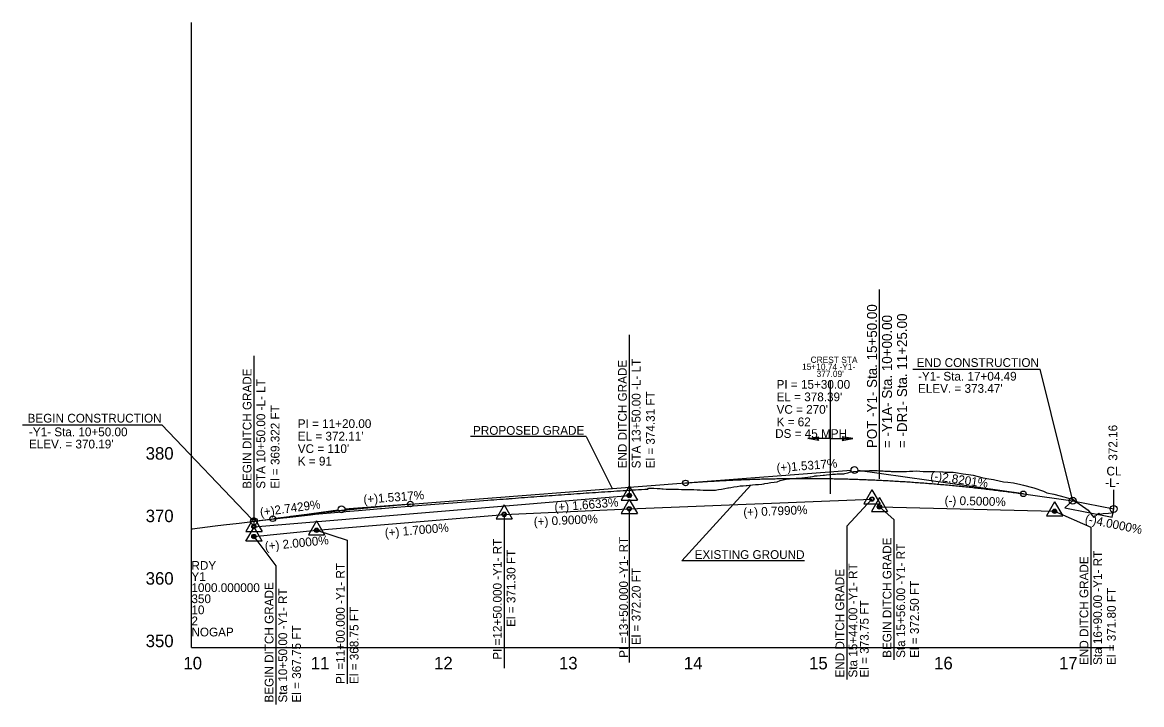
# Model space of a CAD drawing. Extents: x 1625686 to 1640492, y 1161393 to 1175642.
# Drawn here: x 1630069 to 1630964, y 1173490 to 1174036 of the extents above; entities that cross this region are included whole.
import ezdxf

# ---------------------------------------------------------------- set-up
doc = ezdxf.new("R2010")
doc.units = 0
for name, color, linetype in [('Exist Profile Cell', 7, 'Continuous'), ('Exist Vertical Profile Ground Line', 7, 'Continuous'), ('Exist Vertical Profile Horizontal Axis Label Major', 7, 'Continuous'), ('Exist Vertical Profile Vertical Axis Label', 7, 'Continuous'), ('Prop PFL Text', 7, 'Continuous'), ('Prop Plan Preparation Crest', 7, 'Continuous'), ('Prop Vertical Profile Curve Label', 7, 'Continuous'), ('Prop Vertical Profile Ditch Grade Left', 7, 'Continuous'), ('Prop Vertical Profile Ditch Grade Left Label', 7, 'Continuous'), ('Prop Vertical Profile Ditch Grade Right', 7, 'Continuous'), ('Prop Vertical Profile Ditch Grade Right Label', 7, 'Continuous'), ('Prop Vertical Profile Grade', 7, 'Continuous'), ('Prop Vertical Profile Grade Label', 7, 'Continuous'), ('Prop VPI Ditch Grade Left Label', 7, 'Continuous'), ('Prop VPI Ditch Grade Right Label', 7, 'Continuous'), ('Prop VPI Label', 7, 'Continuous')]:
    doc.layers.add(name, color=color, linetype=linetype)

msp = doc.modelspace()

# ---------------------------------------------------------------- linework, layer by layer
at = {"layer": 'Exist Profile Cell'}
for q in [(1630204.31, 1174035.94), (1630941.55, 1173535.94), (1630204.31, 1173535.94)]:
    msp.add_line((1630204.31, 1173535.94), q, dxfattribs=at)
at = {"layer": 'Exist Vertical Profile Ground Line'}
msp.add_lwpolyline([(1630204.31, 1173629.69), (1630205.03, 1173630.93), (1630223.37, 1173633.15), (1630230.03, 1173633.96), (1630242.43, 1173635.46), (1630255.29, 1173637.02), (1630261.5, 1173637.73), (1630280.07, 1173639.86), (1630280.56, 1173639.92), (1630299.62, 1173642.1), (1630305.07, 1173642.73), (1630305.57, 1173642.78), (1630306.15, 1173642.83), (1630318.68, 1173643.91), (1630330.85, 1173644.96), (1630337.74, 1173645.56), (1630352.81, 1173646.86), (1630355.57, 1173647.1), (1630356.33, 1173647.16), (1630362.04, 1173647.62), (1630381.43, 1173649.18), (1630405.79, 1173651.14), (1630406.14, 1173651.16), (1630430.79, 1173653), (1630431.14, 1173653.02), (1630441.12, 1173653.76), (1630443.58, 1173653.94), (1630446.04, 1173654.12), (1630448.5, 1173654.3), (1630450.96, 1173654.48), (1630453.42, 1173654.65), (1630455.89, 1173654.82), (1630457.71, 1173654.95), (1630458.58, 1173655.02), (1630460.81, 1173655.2), (1630463.27, 1173655.4), (1630465.73, 1173655.59), (1630468.19, 1173655.78), (1630470.65, 1173655.97), (1630473.11, 1173656.16), (1630475.57, 1173656.34), (1630478.04, 1173656.53), (1630480.5, 1173656.71), (1630482.96, 1173656.89), (1630485.42, 1173657.08), (1630486.7, 1173657.18), (1630487.88, 1173657.26), (1630490.34, 1173657.44), (1630492.8, 1173657.61), (1630495.26, 1173657.78), (1630497.72, 1173657.95), (1630500.19, 1173658.12), (1630502.65, 1173658.29), (1630505.11, 1173658.45), (1630506.91, 1173658.57), (1630507.57, 1173658.62), (1630510.03, 1173658.8), (1630512.49, 1173658.98), (1630514.95, 1173659.16), (1630517.41, 1173659.34), (1630517.82, 1173659.37), (1630519.87, 1173659.51), (1630522.33, 1173659.68), (1630524.8, 1173659.84), (1630527.26, 1173660), (1630529.72, 1173660.17), (1630532.18, 1173660.33), (1630534.64, 1173660.49), (1630537.1, 1173660.66), (1630539.56, 1173660.82), (1630542.02, 1173660.98), (1630544.48, 1173661.14), (1630546.95, 1173661.3), (1630549.41, 1173661.46), (1630551.87, 1173661.61), (1630554.33, 1173661.76), (1630555.63, 1173661.84), (1630556.79, 1173661.91), (1630557.13, 1173661.93), (1630558.17, 1173662.01), (1630559.38, 1173662.09), (1630561.71, 1173662.24), (1630564.17, 1173662.4), (1630566.63, 1173662.55), (1630569.22, 1173662.65), (1630569.8, 1173663.44), (1630571.56, 1173663.36), (1630574.02, 1173663.26), (1630576.48, 1173663.15), (1630578.94, 1173663.04), (1630580.36, 1173662.97), (1630581.4, 1173662.89), (1630583.86, 1173662.68), (1630585.01, 1173662.59), (1630586.32, 1173662.57), (1630588.78, 1173662.55), (1630591.25, 1173662.51), (1630593.24, 1173662.48), (1630593.71, 1173662.47), (1630596.17, 1173662.39), (1630597.12, 1173662.36), (1630598.63, 1173662.35), (1630601.09, 1173662.34), (1630603.55, 1173662.31), (1630604.98, 1173662.3), (1630606.01, 1173662.24), (1630608.47, 1173662.11), (1630610.93, 1173661.97), (1630613.4, 1173661.82), (1630615.86, 1173661.67), (1630616.16, 1173661.65), (1630618.32, 1173661.73), (1630620.78, 1173661.81), (1630623.24, 1173661.9), (1630624.2, 1173661.93), (1630625.7, 1173662.21), (1630628.16, 1173662.67), (1630630.62, 1173663.12), (1630633.08, 1173663.58), (1630633.7, 1173663.69), (1630635.54, 1173664), (1630638.01, 1173664.42), (1630640.47, 1173664.83), (1630642.93, 1173665.24), (1630643.49, 1173665.33), (1630645.39, 1173665.36), (1630647.85, 1173665.39), (1630648.61, 1173665.4), (1630650.31, 1173665.66), (1630652.77, 1173666.03), (1630655.23, 1173666.36), (1630657.19, 1173666.21), (1630657.69, 1173666.29), (1630660.16, 1173666.7), (1630661.74, 1173666.96), (1630662.62, 1173667.09), (1630665.08, 1173667.45), (1630666.09, 1173667.61), (1630667.54, 1173667.82), (1630670, 1173668.17), (1630672.46, 1173668.57), (1630674.92, 1173669.38), (1630677.38, 1173670.15), (1630679.84, 1173670.62), (1630682.31, 1173670.85), (1630684.77, 1173671.08), (1630685.82, 1173671.18), (1630687.37, 1173671.2), (1630688.04, 1173671.35), (1630689.69, 1173671.48), (1630692.15, 1173671.67), (1630694.61, 1173671.85), (1630694.98, 1173671.88), (1630697.07, 1173672.16), (1630698.91, 1173672.4), (1630699.53, 1173672.53), (1630701.99, 1173673.02), (1630702.63, 1173673.15), (1630704.46, 1173673.3), (1630706.92, 1173673.5), (1630709.38, 1173673.7), (1630709.71, 1173673.73), (1630710.31, 1173673.75), (1630711.84, 1173673.96), (1630714.3, 1173674.22), (1630716.76, 1173674.49), (1630718.02, 1173674.62), (1630719.22, 1173674.66), (1630720.46, 1173674.71), (1630721.68, 1173674.75), (1630724.14, 1173674.84), (1630725.77, 1173674.9), (1630726.6, 1173675.12), (1630729.07, 1173675.76), (1630731.14, 1173676.31), (1630731.53, 1173676.37), (1630733.55, 1173676.72), (1630733.99, 1173676.75), (1630736.45, 1173676.94), (1630738.91, 1173677.14), (1630740.22, 1173677.24), (1630741.37, 1173677.26), (1630741.77, 1173677.33), (1630743.83, 1173677.35), (1630746.29, 1173677.38), (1630748.75, 1173677.4), (1630749.23, 1173677.41), (1630751.22, 1173677.43), (1630752.35, 1173677.45), (1630753.68, 1173677.36), (1630756.14, 1173677.19), (1630757.13, 1173677.12), (1630758.6, 1173677.05), (1630761.06, 1173676.93), (1630762.88, 1173676.84), (1630763.52, 1173676.81), (1630765.07, 1173676.73), (1630765.98, 1173676.72), (1630768.44, 1173676.7), (1630770.9, 1173676.67), (1630772.03, 1173676.66), (1630773.05, 1173676.64), (1630773.37, 1173676.64), (1630775.83, 1173676.78), (1630778.29, 1173676.92), (1630781.07, 1173677.08), (1630783.81, 1173677.12), (1630789.11, 1173676.71), (1630794.24, 1173676.81), (1630798.63, 1173676.8), (1630804.7, 1173676.38), (1630805.22, 1173676.38), (1630806.83, 1173676.25), (1630813.21, 1173676.06), (1630815.12, 1173675.88), (1630821.25, 1173674.93), (1630825.56, 1173674.28), (1630829.28, 1173673.7), (1630836, 1173671.95), (1630837.32, 1173671.57), (1630841.72, 1173670.89), (1630845.35, 1173670.37), (1630846.44, 1173670.13), (1630853.39, 1173668.51), (1630856.88, 1173668.08), (1630861.42, 1173667.53), (1630867.32, 1173666.28), (1630869.46, 1173665.71), (1630876.61, 1173663.87), (1630877.76, 1173663.58), (1630885.53, 1173660.86), (1630888.2, 1173659.74), (1630893.56, 1173658.51), (1630898.64, 1173657.34), (1630901.6, 1173656.45), (1630909.08, 1173654.2), (1630909.63, 1173653.98), (1630911.37, 1173652.69), (1630919.19, 1173647.2), (1630921.12, 1173645.83), (1630921.72, 1173644.96), (1630925.61, 1173639.94), (1630928.49, 1173642.62), (1630929.76, 1173643.51), (1630930.74, 1173642.63), (1630931.71, 1173642.77), (1630933.23, 1173643.03), (1630937.47, 1173643.48), (1630941.55, 1173643.97)], dxfattribs=at)
at = {"layer": 'Prop PFL Text'}
msp.add_line((1630754.31, 1173670.96), (1630754.31, 1173822.24), dxfattribs=at)
at = {"layer": 'Prop Plan Preparation Crest'}
for p, q in [((1630715.05, 1173658.9), (1630715.05, 1173748.84)), ((1630715.05, 1173702.98), (1630697.05, 1173702.98)), ((1630715.05, 1173702.98), (1630733.05, 1173702.98))]:
    msp.add_line(p, q, dxfattribs=at)
for points in [[(1630705.62, 1173701.56), (1630697.05, 1173702.98), (1630705.62, 1173704.41), (1630704.55, 1173702.98)], [(1630724.49, 1173701.56), (1630733.05, 1173702.98), (1630724.49, 1173704.41), (1630725.55, 1173702.98)]]:
    msp.add_lwpolyline(points, close=True, dxfattribs=at)
at = {"layer": 'Prop Vertical Profile Curve Label'}
for p, q in [((1630941.54, 1173646.74), (1630941.54, 1173661.93)), ((1630908.67, 1173653.31), (1630902.4, 1173647.76)), ((1630902.4, 1173647.76), (1630940.23, 1173640.19)), ((1630940.23, 1173640.19), (1630941.54, 1173646.74))]:
    msp.add_line(p, q, dxfattribs=at)
for centre in [(1630599.31, 1173667.55), (1630869.31, 1173658.85), (1630379.31, 1173650.7), (1630269.31, 1173638.95)]:
    msp.add_circle(centre, 2.25, dxfattribs=at)
at = {"layer": 'Prop Vertical Profile Ditch Grade Left'}
msp.add_line((1630254.31, 1173632.55), (1630554.31, 1173657.5), dxfattribs=at)
at = {"layer": 'Prop Vertical Profile Ditch Grade Right'}
msp.add_line((1630754.31, 1173648.44), (1630894.31, 1173644.94), dxfattribs=at)
msp.add_lwpolyline([(1630254.31, 1173624.69), (1630304.31, 1173629.69), (1630454.31, 1173642.44), (1630554.31, 1173646.94), (1630748.31, 1173654.69)], dxfattribs=at)
at = {"layer": 'Prop Vertical Profile Ditch Grade Right Label'}
for p, q in [((1630748.31, 1173662.17), (1630741.86, 1173650.97)), ((1630748.31, 1173662.17), (1630754.81, 1173650.97)), ((1630454.31, 1173649.92), (1630447.86, 1173638.72)), ((1630454.31, 1173649.92), (1630460.81, 1173638.72)), ((1630554.31, 1173654.42), (1630547.86, 1173643.22)), ((1630554.31, 1173654.42), (1630560.81, 1173643.22)), ((1630741.86, 1173650.97), (1630754.81, 1173650.97)), ((1630754.31, 1173655.92), (1630747.86, 1173644.72)), ((1630754.31, 1173655.92), (1630760.81, 1173644.72)), ((1630894.31, 1173652.37), (1630887.86, 1173641.17)), ((1630894.31, 1173652.37), (1630900.81, 1173641.17)), ((1630547.86, 1173643.22), (1630560.81, 1173643.22)), ((1630747.86, 1173644.72), (1630760.81, 1173644.72)), ((1630887.86, 1173641.17), (1630900.81, 1173641.17)), ((1630247.87, 1173620.95), (1630254.33, 1173632.17)), ((1630260.79, 1173620.95), (1630254.33, 1173632.17)), ((1630304.31, 1173637.17), (1630297.86, 1173625.97)), ((1630304.31, 1173637.17), (1630310.81, 1173625.97)), ((1630447.86, 1173638.72), (1630460.81, 1173638.72)), ((1630297.86, 1173625.97), (1630310.81, 1173625.97)), ((1630260.79, 1173620.95), (1630247.87, 1173620.95))]:
    msp.add_line(p, q, dxfattribs=at)
for centre, radius in [((1630748.31, 1173654.69), 1.75), ((1630748.31, 1173654.69), 1.2), ((1630754.31, 1173648.44), 1.75), ((1630754.31, 1173648.44), 1.2), ((1630454.31, 1173642.44), 1.75), ((1630454.31, 1173642.44), 1.2), ((1630554.31, 1173646.94), 1.75), ((1630554.31, 1173646.94), 1.2), ((1630894.31, 1173644.89), 1.75), ((1630894.31, 1173644.89), 1.2), ((1630304.31, 1173629.69), 1.75), ((1630254.31, 1173624.69), 1.75), ((1630254.31, 1173624.69), 1.2), ((1630304.31, 1173629.69), 1.2)]:
    msp.add_circle(centre, radius, dxfattribs=at)
at = {"layer": 'Prop Vertical Profile Grade'}
for p, q in [((1630379.31, 1173650.7), (1630599.31, 1173667.55)), ((1630869.31, 1173658.85), (1630908.8, 1173653.28)), ((1630908.8, 1173653.28), (1630941.54, 1173646.74)), ((1630254.31, 1173636.89), (1630269.31, 1173638.95))]:
    msp.add_line(p, q, dxfattribs=at)
for points in [[(1630599.31, 1173667.55), (1630604.71, 1173667.95), (1630610.11, 1173668.33), (1630615.51, 1173668.68), (1630620.91, 1173669.02), (1630626.31, 1173669.32), (1630631.71, 1173669.61), (1630637.11, 1173669.87), (1630642.51, 1173670.11), (1630647.91, 1173670.32), (1630653.31, 1173670.51), (1630658.71, 1173670.68), (1630664.11, 1173670.82), (1630669.51, 1173670.94), (1630674.91, 1173671.04), (1630680.31, 1173671.11), (1630685.71, 1173671.16), (1630691.11, 1173671.18), (1630696.51, 1173671.19), (1630701.91, 1173671.17), (1630707.31, 1173671.12), (1630712.71, 1173671.05), (1630718.11, 1173670.96), (1630723.51, 1173670.85), (1630728.91, 1173670.71), (1630734.31, 1173670.54), (1630739.71, 1173670.36), (1630745.11, 1173670.15), (1630750.51, 1173669.92), (1630755.91, 1173669.66), (1630761.31, 1173669.38), (1630766.71, 1173669.08), (1630772.11, 1173668.75), (1630777.51, 1173668.4), (1630782.91, 1173668.03), (1630788.31, 1173667.63), (1630793.71, 1173667.21), (1630799.11, 1173666.77), (1630804.51, 1173666.3), (1630809.91, 1173665.81), (1630815.31, 1173665.29), (1630820.71, 1173664.75), (1630826.11, 1173664.19), (1630831.51, 1173663.61), (1630836.91, 1173663), (1630842.31, 1173662.37), (1630847.71, 1173661.71), (1630853.11, 1173661.03), (1630858.51, 1173660.33), (1630863.91, 1173659.6), (1630869.31, 1173658.85)], [(1630269.31, 1173638.95), (1630271.51, 1173639.25), (1630273.71, 1173639.54), (1630275.91, 1173639.84), (1630278.11, 1173640.13), (1630280.31, 1173640.42), (1630282.51, 1173640.71), (1630284.71, 1173640.99), (1630286.91, 1173641.27), (1630289.11, 1173641.55), (1630291.31, 1173641.83), (1630293.51, 1173642.1), (1630295.71, 1173642.37), (1630297.91, 1173642.64), (1630300.11, 1173642.91), (1630302.31, 1173643.17), (1630304.51, 1173643.43), (1630306.71, 1173643.69), (1630308.91, 1173643.94), (1630311.11, 1173644.2), (1630313.31, 1173644.45), (1630315.51, 1173644.69), (1630317.71, 1173644.94), (1630319.91, 1173645.18), (1630322.11, 1173645.42), (1630324.31, 1173645.66), (1630326.51, 1173645.89), (1630328.71, 1173646.12), (1630330.91, 1173646.35), (1630333.11, 1173646.57), (1630335.31, 1173646.8), (1630337.51, 1173647.02), (1630339.71, 1173647.24), (1630341.91, 1173647.45), (1630344.11, 1173647.66), (1630346.31, 1173647.87), (1630348.51, 1173648.08), (1630350.71, 1173648.29), (1630352.91, 1173648.49), (1630355.11, 1173648.69), (1630357.31, 1173648.88), (1630359.51, 1173649.08), (1630361.71, 1173649.27), (1630363.91, 1173649.46), (1630366.11, 1173649.64), (1630368.31, 1173649.82), (1630370.51, 1173650.01), (1630372.71, 1173650.18), (1630374.91, 1173650.36), (1630377.11, 1173650.53), (1630379.31, 1173650.7)]]:
    msp.add_spline(points, degree=3, dxfattribs=at)
at = {"layer": 'Prop VPI Ditch Grade Left Label'}
for p, q in [((1630554.31, 1173785.99), (1630554.31, 1173657.5)), ((1630254.31, 1173769.15), (1630254.31, 1173632.55)), ((1630554.31, 1173664.98), (1630547.86, 1173653.78)), ((1630554.31, 1173664.98), (1630560.81, 1173653.78)), ((1630547.86, 1173653.78), (1630560.81, 1173653.78)), ((1630254.31, 1173640.03), (1630247.86, 1173628.83)), ((1630254.31, 1173640.03), (1630260.81, 1173628.83)), ((1630247.86, 1173628.83), (1630260.81, 1173628.83))]:
    msp.add_line(p, q, dxfattribs=at)
for centre, radius in [((1630554.31, 1173657.5), 1.75), ((1630554.31, 1173657.5), 1.2), ((1630554.31, 1173657.5), 0.5), ((1630254.31, 1173632.55), 1.75), ((1630254.31, 1173632.55), 1.2)]:
    msp.add_circle(centre, radius, dxfattribs=at)
at = {"layer": 'Prop VPI Ditch Grade Right Label'}
for p, q in [((1630454.31, 1173642.44), (1630454.31, 1173519.52)), ((1630554.31, 1173646.94), (1630554.31, 1173524.02))]:
    msp.add_line(p, q, dxfattribs=at)
for points in [[(1630748.31, 1173654.69), (1630728.09, 1173632.91), (1630728.09, 1173510.23)], [(1630754.31, 1173648.44), (1630765.81, 1173638.36), (1630765.81, 1173525.98)], [(1630894.31, 1173644.94), (1630923.27, 1173632.12), (1630923.27, 1173521.97)], [(1630254.31, 1173624.69), (1630271.83, 1173601.13), (1630271.83, 1173490.24)], [(1630304.31, 1173629.69), (1630328.86, 1173621.7), (1630328.86, 1173506.77)]]:
    msp.add_lwpolyline(points, dxfattribs=at)
for centre in [(1630754.31, 1173648.44), (1630894.31, 1173644.94), (1630254.31, 1173624.69)]:
    msp.add_circle(centre, 0.5, dxfattribs=at)
at = {"layer": 'Prop VPI Label'}
for p, q in [((1630780.91, 1173758.61), (1630882.75, 1173758.61)), ((1630908.8, 1173653.28), (1630882.75, 1173758.61)), ((1630069.18, 1173714.12), (1630180.73, 1173714.12)), ((1630252.27, 1173638.73), (1630180.73, 1173714.12)), ((1630519.91, 1173704.62), (1630427.36, 1173704.62)), ((1630519.91, 1173704.62), (1630540.66, 1173663.06)), ((1630599.31, 1173667.55), (1630731.57, 1173677.68)), ((1630869.31, 1173658.85), (1630737.04, 1173677.5)), ((1630596.41, 1173605.31), (1630651.54, 1173665.84)), ((1630379.31, 1173650.7), (1630327.06, 1173646.7)), ((1630269.31, 1173638.95), (1630321.59, 1173646.11)), ((1630694.32, 1173605.31), (1630596.41, 1173605.31))]:
    msp.add_line(p, q, dxfattribs=at)
for centre in [(1630734.31, 1173677.89), (1630908.8, 1173653.28), (1630941.54, 1173646.74), (1630324.31, 1173646.49), (1630254.31, 1173636.89), (1630254.31, 1173636.89)]:
    msp.add_circle(centre, 2.75, dxfattribs=at)

# ---------------------------------------------------------------- texts
at = {"layer": 'Exist Profile Cell'}
for s, p in [('RDY', (1630204.31, 1173598.06)), ('Y1', (1630204.31, 1173589.18)), ('1000.000000', (1630204.31, 1173580.31)), ('350', (1630204.31, 1173571.43)), ('10', (1630204.31, 1173562.56)), ('2', (1630204.31, 1173553.69)), ('NOGAP', (1630204.31, 1173544.81))]:
    msp.add_text(s, height=7, dxfattribs=at).set_placement(p)
at = {"layer": 'Exist Vertical Profile Horizontal Axis Label Major'}
for s, p in [('10', (1630197.9, 1173518.44)), ('11', (1630299.74, 1173518.44)), ('12', (1630398.29, 1173518.44)), ('13', (1630498.12, 1173518.44)), ('14', (1630597.96, 1173518.44)), ('15', (1630698.05, 1173518.44)), ('16', (1630798, 1173518.44)), ('17', (1630897.85, 1173518.44))]:
    msp.add_text(s, height=10, dxfattribs=at).set_placement(p)
at = {"layer": 'Exist Vertical Profile Vertical Axis Label'}
for s, p in [('380', (1630167.75, 1173686.19)), ('370', (1630167.75, 1173636.19)), ('360', (1630167.75, 1173586.19)), ('350', (1630167.75, 1173536.19))]:
    msp.add_text(s, height=10, dxfattribs=at).set_placement(p)
at = {"layer": 'Prop PFL Text'}
for s, p in [('POT -Y1- Sta. 15+50.00', (1630752.33, 1173695.42)), ('= -Y1A- Sta. 10+00.00 ', (1630764.33, 1173695.42)), ('= -DR1- Sta. 11+25.00', (1630776.33, 1173695.42))]:
    msp.add_text(s, height=8, rotation=90, dxfattribs=at).set_placement(p)
at = {"layer": 'Prop Plan Preparation Crest'}
for s, p in [('CREST STA', (1630699.24, 1173763.63)), ('15+10.74 -Y1-', (1630692.4, 1173758.05)), ("377.09'", (1630704.01, 1173752.39))]:
    msp.add_text(s, height=5, rotation=359.75466, dxfattribs=at).set_placement(p)
at = {"layer": 'Prop Vertical Profile Curve Label'}
for s, p in [("VC = 270'", (1630672.04, 1173722.89)), ('K = 62', (1630672.04, 1173712.89)), ('DS = 45 MPH', (1630670.89, 1173703.56)), ("VC = 110'", (1630289.31, 1173691.49)), ('K = 91', (1630289.31, 1173681.49))]:
    msp.add_text(s, height=7, dxfattribs=at).set_placement(p)
at = {"layer": 'Prop Vertical Profile Ditch Grade Left Label'}
msp.add_text('(+) 1.6633%', height=7, rotation=4.75416, dxfattribs=at).set_placement((1630494.76, 1173644.55))
at = {"layer": 'Prop Vertical Profile Ditch Grade Right Label'}
for s, rotation, p in [('(+) 0.7990%', 2.28766, (1630645.61, 1173640.63)), ('(-) 0.5000%', 358.5679, (1630806.3, 1173650.19)), ('(+) 0.9000%', 2.57657, (1630478.08, 1173633.11)), ('(+) 1.7000%', 4.85846, (1630359.15, 1173624.19)), ('(+) 2.0000%', 5.71059, (1630263.31, 1173613.45))]:
    msp.add_text(s, height=7, rotation=rotation, dxfattribs=at).set_placement(p)
at = {"layer": 'Prop Vertical Profile Grade Label'}
for s, rotation, p in [('(+)1.5317%', 4.37947, (1630672.28, 1173676.15)), ('(-)2.8201%', 351.97391, (1630794.71, 1173670.13)), ('(+)1.5317%', 4.37947, (1630342.04, 1173650.86)), ('(+)2.7429%', 7.80899, (1630259.6, 1173640.64)), ('(-)4.0000%', 348.69007, (1630918.13, 1173635.69))]:
    msp.add_text(s, height=7, rotation=rotation, dxfattribs=at).set_placement(p)
at = {"layer": 'Prop VPI Ditch Grade Left Label'}
for s, p in [('END DITCH GRADE', (1630552.31, 1173679.19)), ('STA 13+50.00 -L- LT', (1630563.31, 1173679.19)), ('BEGIN DITCH GRADE', (1630252.31, 1173662.9)), ('STA 10+50.00 -L- LT', (1630263.31, 1173662.9)), ('El = 374.31 FT', (1630574.69, 1173679.19)), ('El = 369.322 FT', (1630274.69, 1173662.9))]:
    msp.add_text(s, height=7, rotation=90, dxfattribs=at).set_placement(p)
at = {"layer": 'Prop VPI Ditch Grade Right Label'}
for s, p in [('PI =12+50.000 -Y1- RT', (1630452.31, 1173526.15)), ('PI =13+50.000 -Y1- RT ', (1630553.24, 1173527.69)), ('BEGIN DITCH GRADE', (1630763.87, 1173527.64)), ('El = 371.30 FT', (1630463.31, 1173552.44)), ('Sta 15+56.00 -Y1- RT', (1630774.81, 1173527.64)), ('END DITCH GRADE', (1630921.25, 1173521.97)), ('Sta 16+90.00 -Y1- RT', (1630932.19, 1173521.97)), ('PI =11+00.000 -Y1- RT', (1630326.86, 1173506.77)), ('El = 372.20 FT', (1630563.31, 1173537.84)), ('END DITCH GRADE', (1630726.15, 1173511.9)), ('Sta 15+44.00 -Y1- RT', (1630736.57, 1173511.9)), ('BEGIN DITCH GRADE', (1630269.89, 1173491.9)), ('El = 372.50 FT', (1630785.81, 1173527.64)), ('Sta 10+50.00 -Y1- RT', (1630280.83, 1173491.9)), ('El = 371.80 FT', (1630943.19, 1173521.97)), ('El = 373.75 FT', (1630745.69, 1173511.9)), ('El = 368.75 FT', (1630337.86, 1173506.77)), ('El = 367.75 FT', (1630291.83, 1173491.9))]:
    msp.add_text(s, height=7, rotation=90, dxfattribs=at).set_placement(p)
at = {"layer": 'Prop VPI Label'}
for s, p in [('END CONSTRUCTION', (1630784.03, 1173760.33)), ('PI = 15+30.00', (1630672.04, 1173742.89)), ('-Y1- Sta. 17+04.49', (1630785.1, 1173749.39)), ("EL = 378.39'", (1630672.04, 1173732.89)), ("ELEV. = 373.47'", (1630785.1, 1173739.64)), ('BEGIN CONSTRUCTION', (1630073.34, 1173715.84)), ('-Y1- Sta. 10+50.00', (1630074.41, 1173704.9)), ('PI = 11+20.00', (1630289.31, 1173711.49)), ('PROPOSED GRADE', (1630429.42, 1173706.06)), ("EL = 372.11'", (1630289.31, 1173701.49)), ("ELEV. = 370.19'", (1630074.41, 1173695.15)), ('CL', (1630935.74, 1173673.53)), ('-L-', (1630934.77, 1173664.35)), ('EXISTING GROUND', (1630606.53, 1173606.76))]:
    msp.add_text(s, height=7, dxfattribs=at).set_placement(p)
msp.add_text('372.16', height=7, rotation=90, dxfattribs=at).set_placement((1630944.38, 1173685.37))

doc.saveas('drawing.dxf')
